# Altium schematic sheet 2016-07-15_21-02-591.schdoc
size 383 x 168 mm; SheetNumber: 1; SheetTotal: 1
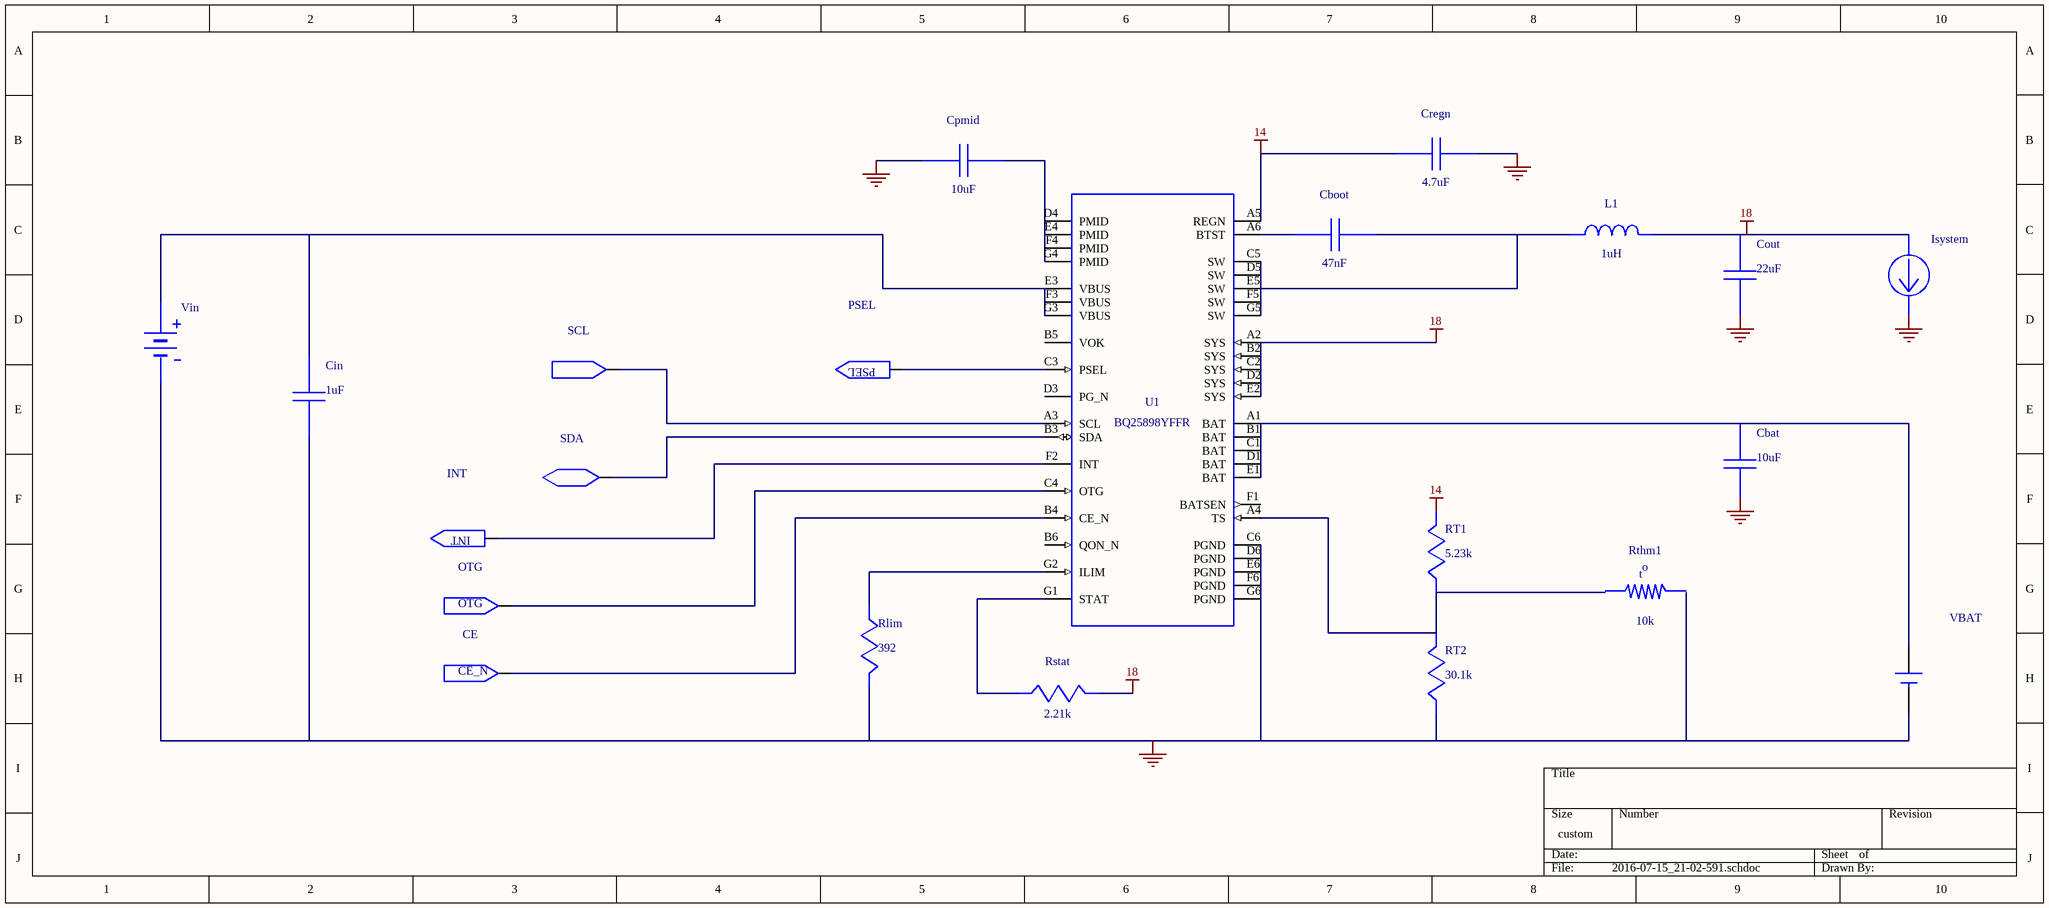
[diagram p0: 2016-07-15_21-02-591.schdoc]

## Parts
Cbat  value 10uF  (hidden comment: GRM219R60J106KE19D)
Cboot  value 47nF  (hidden comment: GRM155R61A473KA01D)
CE  WB_CE_N  (value not drawn)
Cin  value 1uF  (hidden comment: GRM188R61A105KA61D)
Cout  value 22uF  (hidden comment: LMK212BJ226MG-T)
Cpmid  value 10uF  (hidden comment: GRM21BR61A106KE19L)
Cregn  value 4.7uF  (hidden comment: GRM21BR61E475KA12L)
INT  WB_INT_R180  (value not drawn)
Isystem  WB_CURRENT_LOAD  (value not drawn)
L1  value 1uH  (hidden comment: 'VLF252012MT-1R0N')
OTG  WB_OTG  (value not drawn)
PSEL  WB_PSEL_R180  (value not drawn)
Rlim  value 392  (hidden comment: CRCW0402392RFKED)
Rstat  value 2.21k  (hidden comment: CRCW04022K21FKED)
RT1  value 5.23k  (hidden comment: CRCW04025K23FKED)
RT2  value 30.1k  (hidden comment: CRCW040230K1FKED)
Rthm1  value 10k  (hidden comment: NCP15XH103E03RC)
SCL  WB_I2C_SCL  (value not drawn)
SDA  WB_I2C_SDA  (value not drawn)
U1  BQ25898YFFR
VBAT  WB_BATTERY_SINGLE_USFP  (value not drawn)
Vin  WB_BATTERY  (value not drawn)

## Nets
0: Cin.2 Cout.2 Cpmid.2 Cregn.2 Isystem.2(-) Rlim.1 RT2.2 U1.C6(PGND) U1.D6(PGND) U1.E6(PGND) U1.F6(PGND) U1.G6(PGND) VBAT.2(-) Vin.2(-)
14: Cregn.1 RT1.1 U1.A5(REGN)
18: Cout.1 Isystem.1(+) L1.2 Rstat.1 U1.A2(SYS) U1.B2(SYS) U1.C2(SYS) U1.D2(SYS) U1.E2(SYS)
NetCbat_1: Cbat.1 U1.A1(BAT) U1.B1(BAT) U1.C1(BAT) U1.D1(BAT) U1.E1(BAT) VBAT.1(+)
NetCboot_1: Cboot.1 L1.1 U1.C5(SW) U1.D5(SW) U1.E5(SW) U1.F5(SW) U1.G5(SW)
NetCboot_2: Cboot.2 U1.A6(BTST)
NetCE_1: CE.1 U1.B4(CE_N)
NetCin_1: Cin.1 U1.E3(VBUS) U1.F3(VBUS) U1.G3(VBUS) Vin.1(+)
NetCpmid_1: Cpmid.1 U1.D4(PMID) U1.E4(PMID) U1.F4(PMID) U1.G4(PMID)
NetINT_1: INT.1 U1.F2(INT)
NetOTG_1: OTG.1 U1.C4(OTG)
NetPSEL_1: PSEL.1 U1.C3(PSEL)
NetRlim_2: Rlim.2 U1.G2(ILIM)
NetRstat_2: Rstat.2 U1.G1(STAT)
NetRT1_2: RT1.2 RT2.1 U1.A4(TS)
NetSCL_1: SCL.1 U1.A3(SCL)
NetSDA_1: SDA.1 U1.B3(SDA)

Not connected (* = marked no-connect by the designer): Cbat 2; Rthm1 1 2; U1 B5(VOK) B6(QON_N) D3(PG_N) F1(BATSEN)

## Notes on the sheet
- (near PSEL) PSEL
- (near INT) INT
- (near Rthm1) t
- (near Rthm1) o
- (near OTG) OTG
- (near CE) CE_N
- Labels drawn without touching a wire or pin: 0

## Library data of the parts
Cbat = GRM219R60J106KE19D: GRM219R60J106KE1; Manufacturer Name: MuRata
Cboot = GRM155R61A473KA01D: GRM155R61A473KA0; Manufacturer Name: MuRata
Cin = GRM188R61A105KA61D: GRM188R61A105KA6; Manufacturer Name: MuRata
Cout = LMK212BJ226MG-T: Manufacturer Name: Taiyo Yuden
Cpmid = GRM21BR61A106KE19L: GRM21BR61A106KE1; Manufacturer Name: MuRata
Cregn = GRM21BR61E475KA12L: GRM21BR61E475KA1; Manufacturer Name: MuRata
L1 = 'VLF252012MT-1R0N': VLF252012MT-1R0N; Manufacturer Name: TDK
Rlim = CRCW0402392RFKED: Manufacturer Name: Vishay-Dale
Rstat = CRCW04022K21FKED: Manufacturer Name: Vishay-Dale
RT1 = CRCW04025K23FKED: Manufacturer Name: Vishay-Dale
RT2 = CRCW040230K1FKED: Manufacturer Name: Vishay-Dale
Rthm1 = NCP15XH103E03RC: Manufacturer Name: MuRata
U1 = BQ25898YFFR: Manufacturer Name: Texas Instruments
VBAT = WB_BATTERY_SINGLE_USFP: WB_BATTERY_SINGL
